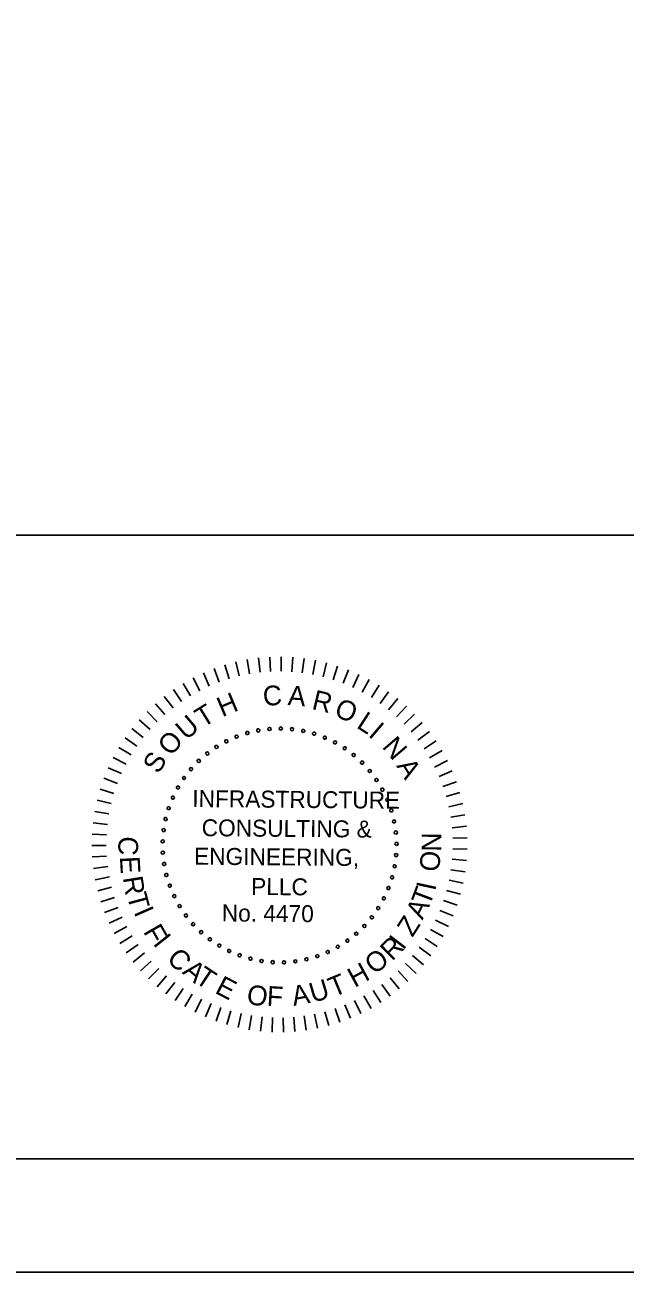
# Model space of a CAD drawing. Extents: x -125.5 to -89.4, y -5.1 to 16.9.
# Drawn here: x -100.32 to -97.68, y -5.07 to 0.43 of the extents above; entities that cross this region are included whole.
import ezdxf

# ---------------------------------------------------------------- set-up
doc = ezdxf.new("R2010")
doc.units = 0
for name, color, linetype in [('BR_BORDER LINES', 7, 'Continuous'), ('BR_TABLE LINES', 7, 'Continuous'), ('BR_TEXT', 7, 'Continuous'), ('Level 31', 7, 'Continuous')]:
    doc.layers.add(name, color=color, linetype=linetype)

msp = doc.modelspace()

# ---------------------------------------------------------------- linework, layer by layer
at = {"layer": 'BR_BORDER LINES'}
for p, q in [((-102.8989, -1.8161), (-97.5337, -1.8161)), ((-123.6994, -4.5662), (-90.0334, -4.5662))]:
    msp.add_line(p, q, dxfattribs=at)
at = {"layer": 'BR_TABLE LINES'}
msp.add_lwpolyline([(-123.6994, 16.4338), (-90.0334, 16.4338), (-90.0334, -4.5662), (-123.6994, -4.5662)], close=True, dxfattribs=at)
at = {"layer": 'BR_TEXT'}
for p, q in [((-99.2931, -2.3579), (-99.2858, -2.4212)), ((-99.2427, -2.3538), (-99.2394, -2.4174)), ((-99.1923, -2.3527), (-99.1928, -2.4164)), ((-99.1418, -2.3548), (-99.1462, -2.4183)), ((-99.0916, -2.3599), (-99.0999, -2.423)), ((-99.489, -2.4048), (-99.4667, -2.4644)), ((-99.4412, -2.3886), (-99.4226, -2.4495)), ((-99.3925, -2.3754), (-99.3776, -2.4373)), ((-99.343, -2.3651), (-99.332, -2.4278)), ((-99.0418, -2.368), (-99.0539, -2.4305)), ((-98.9925, -2.3792), (-99.0084, -2.4408)), ((-98.9441, -2.3933), (-98.9637, -2.4539)), ((-98.8966, -2.4104), (-98.9199, -2.4696)), ((-99.6253, -2.4703), (-99.5926, -2.5249)), ((-99.5813, -2.4457), (-99.5519, -2.5022)), ((-99.5358, -2.4238), (-99.5099, -2.482)), ((-98.8502, -2.4303), (-98.877, -2.488)), ((-98.8051, -2.453), (-98.8354, -2.509)), ((-99.7086, -2.5273), (-99.6694, -2.5775)), ((-99.6678, -2.4975), (-99.6318, -2.55)), ((-98.7615, -2.4785), (-98.7952, -2.5325)), ((-98.7195, -2.5065), (-98.7564, -2.5584)), ((-99.7475, -2.5595), (-99.7053, -2.6072)), ((-98.6793, -2.5371), (-98.7193, -2.5866)), ((-98.6411, -2.57), (-98.684, -2.617)), ((-99.819, -2.6308), (-99.7713, -2.673)), ((-99.7843, -2.5941), (-99.7393, -2.6391)), ((-98.6049, -2.6052), (-98.6506, -2.6495)), ((-99.8513, -2.6695), (-99.8012, -2.7087)), ((-98.571, -2.6426), (-98.6193, -2.684)), ((-98.5393, -2.6819), (-98.5901, -2.7204)), ((-99.8813, -2.7102), (-99.8288, -2.7463)), ((-98.5102, -2.7232), (-98.5632, -2.7584)), ((-99.9334, -2.7965), (-99.877, -2.826)), ((-99.9087, -2.7526), (-99.8541, -2.7854)), ((-98.4836, -2.7661), (-98.5387, -2.798)), ((-99.9555, -2.842), (-99.8973, -2.8679)), ((-98.4597, -2.8105), (-98.5166, -2.839)), ((-98.4385, -2.8563), (-98.497, -2.8813)), ((-99.9747, -2.8886), (-99.9151, -2.911)), ((-98.4202, -2.9034), (-98.4801, -2.9248)), ((-99.991, -2.9364), (-99.9302, -2.9551)), ((-98.4047, -2.9514), (-98.4659, -2.9691)), ((-100.0044, -2.9851), (-99.9426, -3)), ((-98.3922, -3.0004), (-98.4544, -3.0143)), ((-100.0149, -3.0345), (-99.9522, -3.0456)), ((-98.3828, -3.05), (-98.4456, -3.0601)), ((-100.0266, -3.1347), (-99.963, -3.1382)), ((-100.0222, -3.0844), (-99.959, -3.0917)), ((-98.3763, -3.1), (-98.4397, -3.1063)), ((-100.0278, -3.1852), (-99.9641, -3.1847)), ((-98.373, -3.1504), (-98.4366, -3.1528)), ((-100.026, -3.2356), (-99.9625, -3.2313)), ((-98.3727, -3.2009), (-98.4363, -3.1994)), ((-100.0211, -3.2859), (-99.9579, -3.2777)), ((-98.3813, -3.3014), (-98.4443, -3.2922)), ((-98.3755, -3.2513), (-98.4389, -3.2459)), ((-100.0131, -3.3357), (-99.9506, -3.3237)), ((-98.3902, -3.3511), (-98.4525, -3.3381)), ((-100.0021, -3.385), (-99.9405, -3.3692)), ((-98.4021, -3.4002), (-98.4635, -3.3834)), ((-99.9882, -3.4335), (-99.9276, -3.414)), ((-99.9713, -3.4811), (-99.912, -3.4579)), ((-98.417, -3.4484), (-98.4773, -3.4279)), ((-99.9515, -3.5276), (-99.8937, -3.5008)), ((-98.4554, -3.5417), (-98.5128, -3.514)), ((-98.4348, -3.4957), (-98.4937, -3.4715)), ((-99.929, -3.5727), (-99.8729, -3.5425)), ((-98.4789, -3.5865), (-98.5344, -3.5553)), ((-99.9037, -3.6164), (-99.8496, -3.5828)), ((-99.8758, -3.6585), (-99.8239, -3.6217)), ((-98.505, -3.6297), (-98.5585, -3.5952)), ((-99.8454, -3.6988), (-99.7958, -3.6589)), ((-98.5648, -3.7109), (-98.6137, -3.6702)), ((-98.5336, -3.6712), (-98.5849, -3.6335)), ((-99.8126, -3.7372), (-99.7655, -3.6943)), ((-99.7775, -3.7735), (-99.7331, -3.7278)), ((-98.6341, -3.7843), (-98.6777, -3.7379)), ((-98.5983, -3.7487), (-98.6447, -3.705)), ((-99.7403, -3.8076), (-99.6988, -3.7593)), ((-99.701, -3.8393), (-99.6626, -3.7886)), ((-98.672, -3.8177), (-98.7126, -3.7687)), ((-99.6599, -3.8687), (-99.6246, -3.8157)), ((-99.6171, -3.8954), (-99.5851, -3.8404)), ((-98.7967, -3.9032), (-98.8278, -3.8476)), ((-98.7534, -3.8772), (-98.7879, -3.8237)), ((-98.7118, -3.8487), (-98.7494, -3.7974)), ((-99.5728, -3.9195), (-99.5442, -3.8626)), ((-99.527, -3.9408), (-99.5019, -3.8823)), ((-99.48, -3.9594), (-99.4586, -3.8994)), ((-98.935, -3.9645), (-98.9555, -3.9042)), ((-98.8877, -3.9469), (-98.9118, -3.888)), ((-98.8416, -3.9264), (-98.8692, -3.8691)), ((-99.432, -3.975), (-99.4143, -3.9138)), ((-99.3832, -3.9876), (-99.3692, -3.9255)), ((-99.3336, -3.9973), (-99.3234, -3.9344)), ((-99.2836, -4.0039), (-99.2772, -3.9406)), ((-99.2332, -4.0075), (-99.2307, -3.9438)), ((-99.1827, -4.0079), (-99.1841, -3.9443)), ((-99.1323, -4.0053), (-99.1376, -3.9419)), ((-99.0821, -3.9997), (-99.0913, -3.9367)), ((-99.0324, -3.991), (-99.0454, -3.9286)), ((-98.9833, -3.9792), (-99.0001, -3.9178))]:
    msp.add_line(p, q, dxfattribs=at)
for centre, start, end in [((-99.3424, -2.6889), 16.1422, 196.1422), ((-99.3424, -2.6889), 196.1422, 16.1422), ((-99.2939, -2.6775), 10.6038, 190.6038), ((-99.2939, -2.6775), 190.6038, 10.6038), ((-99.2445, -2.6708), 5.0653, 185.0653), ((-99.2445, -2.6708), 185.0653, 5.0653), ((-99.1947, -2.6689), 359.5268, 179.5268), ((-99.1947, -2.6689), 179.5268, 359.5268), ((-99.145, -2.6718), 173.9884, 353.9884), ((-99.145, -2.6718), 353.9884, 173.9884), ((-99.0957, -2.6795), 168.4499, 348.4499), ((-99.0957, -2.6795), 348.4499, 168.4499), ((-99.0475, -2.6919), 162.9114, 342.9114), ((-99.0475, -2.6919), 342.9114, 162.9114), ((-99.4782, -2.7503), 32.7576, 212.7576), ((-99.4782, -2.7503), 212.7576, 32.7576), ((-99.435, -2.7255), 27.2191, 207.2191), ((-99.435, -2.7255), 207.2191, 27.2191), ((-99.3896, -2.705), 21.6807, 201.6807), ((-99.3896, -2.705), 201.6807, 21.6807), ((-99.0006, -2.709), 157.373, 337.373), ((-99.0006, -2.709), 337.373, 157.373), ((-98.9557, -2.7304), 151.8345, 331.8345), ((-98.9557, -2.7304), 331.8345, 151.8345), ((-98.913, -2.7561), 326.2961, 146.2961), ((-99.5564, -2.8119), 43.8345, 223.8345), ((-99.5188, -2.7792), 38.2961, 218.2961), ((-99.5188, -2.7792), 218.2961, 38.2961), ((-98.913, -2.7561), 146.2961, 326.2961), ((-98.873, -2.7858), 140.7576, 320.7576), ((-98.873, -2.7858), 320.7576, 140.7576), ((-99.5907, -2.848), 49.373, 229.373), ((-99.5907, -2.848), 229.373, 49.373), ((-99.5564, -2.8119), 223.8345, 43.8345), ((-98.836, -2.8192), 135.2191, 315.2191), ((-98.836, -2.8192), 315.2191, 135.2191), ((-98.8024, -2.8561), 129.6807, 309.6807), ((-98.8024, -2.8561), 309.6807, 129.6807), ((-99.6214, -2.8873), 54.9114, 234.9114), ((-99.6214, -2.8873), 234.9114, 54.9114), ((-98.7726, -2.896), 124.1422, 304.1422), ((-98.7726, -2.896), 304.1422, 124.1422), ((-99.6706, -2.9738), 65.9884, 245.9884), ((-99.6706, -2.9738), 245.9884, 65.9884), ((-99.6481, -2.9293), 60.4499, 240.4499), ((-99.6481, -2.9293), 240.4499, 60.4499), ((-98.7467, -2.9386), 118.6038, 298.6038), ((-98.7467, -2.9386), 298.6038, 118.6038), ((-99.6888, -3.0202), 71.5268, 251.5268), ((-99.6888, -3.0202), 251.5268, 71.5268), ((-98.7251, -2.9835), 113.0653, 293.0653), ((-98.7251, -2.9835), 293.0653, 113.0653), ((-98.7079, -3.0302), 107.5268, 287.5268), ((-98.7079, -3.0302), 287.5268, 107.5268), ((-99.7024, -3.0681), 77.0653, 257.0653), ((-99.7024, -3.0681), 257.0653, 77.0653), ((-98.6953, -3.0785), 101.9884, 281.9884), ((-98.6953, -3.0785), 281.9884, 101.9884), ((-99.7113, -3.1172), 82.6038, 262.6038), ((-99.7113, -3.1172), 262.6038, 82.6038), ((-98.6874, -3.1277), 96.4499, 276.4499), ((-98.6874, -3.1277), 276.4499, 96.4499), ((-99.7154, -3.1668), 88.1422, 268.1422), ((-99.7154, -3.1668), 268.1422, 88.1422), ((-98.6843, -3.1774), 90.9114, 270.9114), ((-98.6843, -3.1774), 270.9114, 90.9114), ((-99.7147, -3.2167), 93.6807, 273.6807), ((-99.7147, -3.2167), 273.6807, 93.6807), ((-98.686, -3.2272), 85.373, 265.373), ((-98.686, -3.2272), 265.373, 85.373), ((-99.7092, -3.2662), 99.2191, 279.2191), ((-99.7092, -3.2662), 279.2191, 99.2191), ((-98.6926, -3.2766), 79.8345, 259.8345), ((-98.6926, -3.2766), 259.8345, 79.8345), ((-99.6989, -3.3149), 104.7576, 284.7576), ((-99.6989, -3.3149), 284.7576, 104.7576), ((-98.7038, -3.3251), 74.2961, 254.2961), ((-98.7038, -3.3251), 254.2961, 74.2961), ((-99.684, -3.3625), 110.2961, 290.2961), ((-99.684, -3.3625), 290.2961, 110.2961), ((-99.6646, -3.4084), 115.8345, 295.8345), ((-99.6646, -3.4084), 295.8345, 115.8345), ((-98.7197, -3.3724), 68.7576, 248.7576), ((-98.7197, -3.3724), 248.7576, 68.7576), ((-99.6408, -3.4522), 121.373, 301.373), ((-99.6408, -3.4522), 301.373, 121.373), ((-98.7647, -3.4611), 57.6807, 237.6807), ((-98.7647, -3.4611), 237.6807, 57.6807), ((-98.7401, -3.4178), 63.2191, 243.2191), ((-98.7401, -3.4178), 243.2191, 63.2191), ((-99.6129, -3.4935), 126.9114, 306.9114), ((-99.6129, -3.4935), 306.9114, 126.9114), ((-98.7934, -3.5019), 52.1422, 232.1422), ((-98.7934, -3.5019), 232.1422, 52.1422), ((-99.5812, -3.5319), 132.4499, 312.4499), ((-99.5812, -3.5319), 312.4499, 132.4499), ((-99.5459, -3.5671), 137.9884, 317.9884), ((-99.5459, -3.5671), 317.9884, 137.9884), ((-98.862, -3.5741), 41.0653, 221.0653), ((-98.862, -3.5741), 221.0653, 41.0653), ((-98.826, -3.5396), 46.6038, 226.6038), ((-98.826, -3.5396), 226.6038, 46.6038), ((-99.5074, -3.5987), 143.5268, 323.5268), ((-99.5074, -3.5987), 323.5268, 143.5268), ((-99.466, -3.6264), 149.0653, 329.0653), ((-99.466, -3.6264), 329.0653, 149.0653), ((-98.9431, -3.6317), 29.9884, 209.9884), ((-98.9431, -3.6317), 209.9884, 29.9884), ((-98.9012, -3.6049), 35.5268, 215.5268), ((-98.9012, -3.6049), 215.5268, 35.5268), ((-99.4221, -3.65), 154.6038, 334.6038), ((-99.4221, -3.65), 334.6038, 154.6038), ((-99.3761, -3.6693), 160.1422, 340.1422), ((-99.3761, -3.6693), 340.1422, 160.1422), ((-99.3285, -3.684), 165.6807, 345.6807), ((-99.3285, -3.684), 345.6807, 165.6807), ((-99.0817, -3.6865), 13.373, 193.373), ((-99.0817, -3.6865), 193.373, 13.373), ((-99.0338, -3.6728), 18.9114, 198.9114), ((-99.0338, -3.6728), 198.9114, 18.9114), ((-98.9875, -3.6545), 24.4499, 204.4499), ((-98.9875, -3.6545), 204.4499, 24.4499), ((-99.2797, -3.6941), 351.2191, 171.2191), ((-99.2797, -3.6941), 171.2191, 351.2191), ((-99.2302, -3.6994), 356.7576, 176.7576), ((-99.2302, -3.6994), 176.7576, 356.7576), ((-99.1803, -3.6999), 2.2961, 182.2961), ((-99.1803, -3.6999), 182.2961, 2.2961), ((-99.1307, -3.6956), 7.8345, 187.8345), ((-99.1307, -3.6956), 187.8345, 7.8345)]:
    msp.add_arc(centre, 0.00701, start, end, dxfattribs=at)
at = {"layer": 'Level 31'}
msp.add_lwpolyline([(-125.5328, -5.0661), (-89.5328, -5.0661), (-89.5328, 16.9339), (-125.5328, 16.9339)], close=True, dxfattribs=at)

# ---------------------------------------------------------------- texts
at = {"layer": 'BR_TEXT'}
for s, height, rotation, p in [('H', 0.0872, 22.7882, (-99.453, -2.6197)), ('C', 0.0872, 4.7281, (-99.2702, -2.5703)), ('A', 0.0872, 355.6981, (-99.1657, -2.5654)), ('R', 0.0872, 346.6681, (-99.0615, -2.5824)), ('T', 0.0872, 31.8182, (-99.5379, -2.6674)), ('O', 0.0872, 337.638, (-98.9637, -2.6122)), ('U', 0.0872, 40.8482, (-99.6112, -2.7235)), ('L', 0.0872, 327.108, (-98.8649, -2.6626)), ('O', 0.0872, 49.8782, (-99.6782, -2.7945)), ('I', 0.0872, 319.578, (-98.8123, -2.7005)), ('N', 0.0872, 310.548, (-98.7515, -2.7512)), ('S', 0.0872, 58.9083, (-99.7336, -2.8727)), ('A', 0.0872, 301.5179, (-98.6864, -2.8336)), ('INFRASTRUCTURE', 0.074771, 359.5268, (-99.585, -3.0152)), ('CONSULTING &', 0.074771, 359.5268, (-99.5437, -3.1438)), ('C', 0.0872, 267.025, (-99.9086, -3.1426)), ('N', 0.0872, 89.2085, (-98.4872, -3.2124)), ('E', 0.0872, 273.025, (-99.9042, -3.2342)), ('ENGINEERING,', 0.074771, 359.5268, (-99.5773, -3.2693)), ('O', 0.0872, 83.2085, (-98.4982, -3.3038)), ('R', 0.0872, 279.025, (-99.8914, -3.3265)), ('PLLC', 0.07477, 359.5268, (-99.3256, -3.4028)), ('I', 0.0872, 77.9093, (-98.5137, -3.3881)), ('T', 0.0872, 285.025, (-99.874, -3.4053)), ('T', 0.0872, 69.3954, (-98.5394, -3.4556)), ('I', 0.0872, 293.7713, (-99.8443, -3.4784)), ('No. 4470', 0.07477, 359.5268, (-99.4551, -3.5197)), ('A', 0.0872, 63.3954, (-98.5702, -3.516)), ('Z', 0.0872, 57.3954, (-98.6141, -3.5923)), ('F', 0.0872, 299.7713, (-99.8031, -3.5644)), ('I', 0.0872, 308.5268, (-99.761, -3.6183)), ('R', 0.0872, 44.5268, (-98.7045, -3.6973)), ('I', 0.0872, 52.3339, (-98.6551, -3.65)), ('C', 0.0872, 314.5268, (-99.7017, -3.6884)), ('O', 0.0872, 38.5268, (-98.7811, -3.7572)), ('A', 0.0872, 320.5268, (-99.6325, -3.747)), ('T', 0.0872, 326.5268, (-99.5781, -3.7855)), ('H', 0.0872, 28.5268, (-98.8692, -3.8132)), ('E', 0.0872, 332.5268, (-99.4895, -3.8332)), ('U', 0.0872, 16.5268, (-99.0541, -3.8794)), ('T', 0.0872, 22.5268, (-98.9624, -3.855)), ('O', 0.0872, 350.5268, (-99.3494, -3.8821)), ('F', 0.0872, 356.5268, (-99.2579, -3.8912)), ('A', 0.0872, 10.5268, (-99.138, -3.8929))]:
    msp.add_text(s, height=height, rotation=rotation, dxfattribs=at).set_placement(p)

doc.saveas('drawing.dxf')
